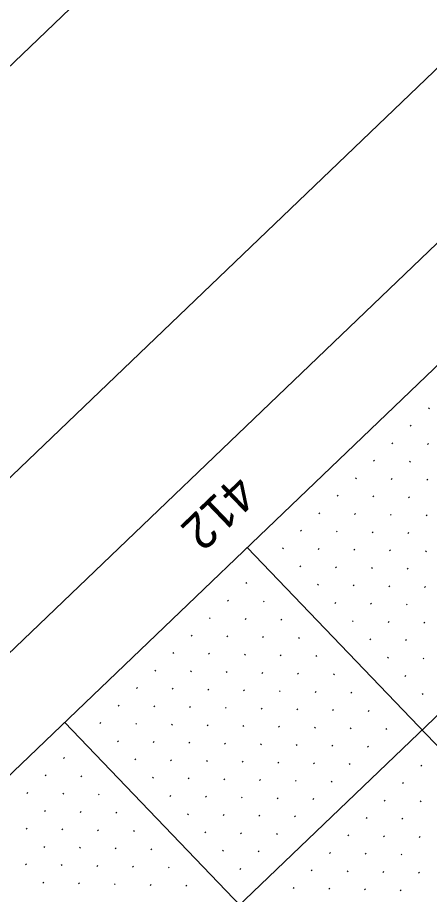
# Model space of a CAD drawing. Extents: x 2148987 to 2151117, y 142806 to 144993.
# Drawn here: x 2149649.5 to 2149731, y 144141.4 to 144315 of the extents above; entities that cross this region are included whole.
import ezdxf

# ---------------------------------------------------------------- set-up
doc = ezdxf.new("R2010")
doc.units = 0
for name, color, linetype in [('BASELINE', 7, 'Continuous'), ('PR_ABUT_PH3', 7, 'Continuous'), ('PR_PIER_PH3', 7, 'Continuous'), ('PR_Road_Concrete', 7, 'Continuous'), ('SHT_Profile_Grid_Minor', 7, 'Continuous'), ('Wall D Bore Txt', 7, 'Continuous')]:
    doc.layers.add(name, color=color, linetype=linetype)

msp = doc.modelspace()

# ---------------------------------------------------------------- linework, layer by layer
at = {"layer": 'BASELINE'}
msp.add_lwpolyline([(2151029.45, 144024.32), (2149802.07, 142848.08), (2149040.98, 143642.27), (2150268.36, 144818.51)], close=True, dxfattribs=at)
at = {"layer": 'PR_ABUT_PH3'}
msp.add_lwpolyline([(2151117.11, 144051.19), (2149817.52, 142805.76), (2148987.24, 143672.15), (2150286.82, 144917.58)], close=True, dxfattribs=at)
at = {"layer": 'PR_PIER_PH3'}
for p, q in [((2150261.97, 144684.26), (2149124.83, 143594.52)), ((2149694.9, 144210.09), (2149989.02, 143903.18)), ((2149658.8, 144175.49), (2149952.92, 143868.59))]:
    msp.add_line(p, q, dxfattribs=at)
at = {"layer": 'PR_Road_Concrete'}
msp.add_line((2150227.37, 144720.36), (2149279.76, 143812.24), dxfattribs=at)
msp.add_lwpolyline([(2150941.76, 143974.91), (2149804.63, 142885.16), (2149078.13, 143643.25), (2150215.26, 144733)], close=True, dxfattribs=at)
at = {"layer": 'SHT_Profile_Grid_Minor'}
for p, q in [((2149730.94, 144237.7), (2149730.76, 144237.52)), ((2149727.33, 144234.24), (2149727.15, 144234.06)), ((2149723.72, 144230.78), (2149723.54, 144230.61)), ((2149730.79, 144230.63), (2149730.61, 144230.45)), ((2149720.11, 144227.32), (2149719.93, 144227.15)), ((2149727.18, 144227.17), (2149727, 144227)), ((2149716.5, 144223.86), (2149716.32, 144223.69)), ((2149723.57, 144223.71), (2149723.39, 144223.54)), ((2149730.64, 144223.56), (2149730.46, 144223.39)), ((2149712.89, 144220.4), (2149712.71, 144220.23)), ((2149719.96, 144220.25), (2149719.78, 144220.08)), ((2149727.03, 144220.1), (2149726.85, 144219.93)), ((2149709.28, 144216.94), (2149709.1, 144216.77)), ((2149716.35, 144216.79), (2149716.17, 144216.62)), ((2149723.42, 144216.64), (2149723.24, 144216.47)), ((2149730.49, 144216.49), (2149730.31, 144216.32)), ((2149705.67, 144213.48), (2149705.49, 144213.31)), ((2149712.74, 144213.33), (2149712.56, 144213.16)), ((2149719.81, 144213.18), (2149719.63, 144213.01)), ((2149726.88, 144213.03), (2149726.7, 144212.86)), ((2149702.06, 144210.02), (2149701.88, 144209.85)), ((2149709.13, 144209.87), (2149708.95, 144209.7)), ((2149716.2, 144209.72), (2149716.02, 144209.55)), ((2149723.27, 144209.57), (2149723.09, 144209.4)), ((2149730.34, 144209.42), (2149730.16, 144209.25)), ((2149705.52, 144206.41), (2149705.34, 144206.24)), ((2149712.59, 144206.26), (2149712.41, 144206.09)), ((2149719.66, 144206.11), (2149719.48, 144205.94)), ((2149726.73, 144205.96), (2149726.55, 144205.79)), ((2149694.84, 144203.1), (2149694.66, 144202.93)), ((2149708.98, 144202.8), (2149708.8, 144202.63)), ((2149716.05, 144202.65), (2149715.87, 144202.48)), ((2149723.12, 144202.5), (2149722.94, 144202.33)), ((2149730.19, 144202.35), (2149730.01, 144202.18)), ((2149691.23, 144199.64), (2149691.05, 144199.47)), ((2149698.3, 144199.49), (2149698.12, 144199.32)), ((2149712.44, 144199.19), (2149712.26, 144199.02)), ((2149719.51, 144199.04), (2149719.33, 144198.87)), ((2149726.58, 144198.89), (2149726.4, 144198.72)), ((2149687.62, 144196.18), (2149687.44, 144196.01)), ((2149694.69, 144196.03), (2149694.51, 144195.86)), ((2149701.76, 144195.88), (2149701.58, 144195.71)), ((2149715.9, 144195.58), (2149715.72, 144195.41)), ((2149722.97, 144195.43), (2149722.79, 144195.26)), ((2149730.04, 144195.28), (2149729.86, 144195.11)), ((2149684.01, 144192.72), (2149683.83, 144192.55)), ((2149691.08, 144192.57), (2149690.9, 144192.4)), ((2149698.15, 144192.42), (2149697.97, 144192.25)), ((2149705.22, 144192.27), (2149705.04, 144192.1)), ((2149719.36, 144191.97), (2149719.18, 144191.8)), ((2149726.43, 144191.82), (2149726.25, 144191.65)), ((2149680.4, 144189.26), (2149680.22, 144189.09)), ((2149687.47, 144189.11), (2149687.29, 144188.94)), ((2149694.54, 144188.96), (2149694.36, 144188.79)), ((2149701.61, 144188.81), (2149701.43, 144188.64)), ((2149708.68, 144188.66), (2149708.5, 144188.49)), ((2149722.82, 144188.36), (2149722.64, 144188.19)), ((2149729.89, 144188.21), (2149729.71, 144188.04)), ((2149676.79, 144185.8), (2149676.61, 144185.63)), ((2149683.86, 144185.65), (2149683.68, 144185.48)), ((2149690.93, 144185.5), (2149690.75, 144185.33)), ((2149698, 144185.35), (2149697.82, 144185.18)), ((2149705.07, 144185.2), (2149704.89, 144185.03)), ((2149712.14, 144185.05), (2149711.96, 144184.88)), ((2149726.28, 144184.75), (2149726.1, 144184.58)), ((2149673.18, 144182.35), (2149673, 144182.17)), ((2149680.25, 144182.19), (2149680.07, 144182.02)), ((2149687.32, 144182.04), (2149687.14, 144181.87)), ((2149694.39, 144181.89), (2149694.21, 144181.72)), ((2149701.46, 144181.74), (2149701.28, 144181.57)), ((2149708.53, 144181.59), (2149708.35, 144181.42)), ((2149715.6, 144181.44), (2149715.42, 144181.27)), ((2149729.74, 144181.14), (2149729.56, 144180.97)), ((2149669.57, 144178.89), (2149669.39, 144178.71)), ((2149676.64, 144178.74), (2149676.46, 144178.56)), ((2149683.71, 144178.58), (2149683.53, 144178.41)), ((2149690.78, 144178.43), (2149690.6, 144178.26)), ((2149697.85, 144178.28), (2149697.67, 144178.11)), ((2149704.92, 144178.13), (2149704.74, 144177.96)), ((2149711.99, 144177.98), (2149711.81, 144177.81)), ((2149719.06, 144177.83), (2149718.88, 144177.66)), ((2149665.96, 144175.43), (2149665.78, 144175.25)), ((2149673.03, 144175.28), (2149672.85, 144175.1)), ((2149680.1, 144175.13), (2149679.92, 144174.95)), ((2149687.17, 144174.97), (2149686.99, 144174.8)), ((2149694.24, 144174.82), (2149694.06, 144174.65)), ((2149701.31, 144174.67), (2149701.13, 144174.5)), ((2149708.38, 144174.52), (2149708.2, 144174.35)), ((2149715.45, 144174.37), (2149715.27, 144174.2)), ((2149722.52, 144174.22), (2149722.34, 144174.05)), ((2149669.42, 144171.82), (2149669.24, 144171.64)), ((2149676.49, 144171.67), (2149676.31, 144171.49)), ((2149683.56, 144171.52), (2149683.38, 144171.34)), ((2149690.63, 144171.36), (2149690.45, 144171.19)), ((2149697.7, 144171.21), (2149697.52, 144171.04)), ((2149704.77, 144171.06), (2149704.59, 144170.89)), ((2149711.84, 144170.91), (2149711.66, 144170.74)), ((2149718.91, 144170.76), (2149718.73, 144170.59)), ((2149658.74, 144168.51), (2149658.56, 144168.33)), ((2149672.88, 144168.21), (2149672.7, 144168.03)), ((2149679.95, 144168.06), (2149679.77, 144167.88)), ((2149687.02, 144167.91), (2149686.84, 144167.73)), ((2149694.09, 144167.75), (2149693.91, 144167.58)), ((2149701.16, 144167.6), (2149700.98, 144167.43)), ((2149708.23, 144167.45), (2149708.05, 144167.28)), ((2149715.3, 144167.3), (2149715.12, 144167.13)), ((2149729.44, 144167), (2149729.26, 144166.83)), ((2149655.13, 144165.05), (2149654.95, 144164.87)), ((2149662.2, 144164.9), (2149662.02, 144164.72)), ((2149676.34, 144164.6), (2149676.16, 144164.42)), ((2149683.41, 144164.45), (2149683.23, 144164.27)), ((2149690.48, 144164.3), (2149690.3, 144164.12)), ((2149697.55, 144164.15), (2149697.37, 144163.97)), ((2149704.62, 144163.99), (2149704.44, 144163.82)), ((2149711.69, 144163.84), (2149711.51, 144163.67)), ((2149725.83, 144163.54), (2149725.65, 144163.37)), ((2149651.52, 144161.59), (2149651.34, 144161.42)), ((2149658.59, 144161.44), (2149658.41, 144161.26)), ((2149665.66, 144161.29), (2149665.48, 144161.11)), ((2149679.8, 144160.99), (2149679.62, 144160.81)), ((2149686.87, 144160.84), (2149686.69, 144160.66)), ((2149693.94, 144160.69), (2149693.76, 144160.51)), ((2149701.01, 144160.54), (2149700.83, 144160.36)), ((2149708.08, 144160.38), (2149707.9, 144160.21)), ((2149722.22, 144160.08), (2149722.04, 144159.91)), ((2149729.29, 144159.93), (2149729.11, 144159.76)), ((2149654.98, 144157.98), (2149654.8, 144157.81)), ((2149662.05, 144157.83), (2149661.87, 144157.65)), ((2149669.12, 144157.68), (2149668.94, 144157.5)), ((2149683.26, 144157.38), (2149683.08, 144157.2)), ((2149690.33, 144157.23), (2149690.15, 144157.05)), ((2149697.4, 144157.08), (2149697.22, 144156.9)), ((2149704.47, 144156.93), (2149704.29, 144156.75)), ((2149718.61, 144156.62), (2149718.43, 144156.45)), ((2149725.68, 144156.47), (2149725.5, 144156.3)), ((2149651.37, 144154.52), (2149651.19, 144154.35)), ((2149658.44, 144154.37), (2149658.26, 144154.2)), ((2149665.51, 144154.22), (2149665.33, 144154.04)), ((2149672.58, 144154.07), (2149672.4, 144153.89)), ((2149686.72, 144153.77), (2149686.54, 144153.59)), ((2149693.79, 144153.62), (2149693.61, 144153.44)), ((2149700.86, 144153.47), (2149700.68, 144153.29)), ((2149715, 144153.16), (2149714.82, 144152.99)), ((2149722.07, 144153.01), (2149721.89, 144152.84)), ((2149729.14, 144152.86), (2149728.96, 144152.69)), ((2149654.83, 144150.91), (2149654.65, 144150.74)), ((2149661.9, 144150.76), (2149661.72, 144150.59)), ((2149668.97, 144150.61), (2149668.79, 144150.43)), ((2149676.04, 144150.46), (2149675.86, 144150.28)), ((2149690.18, 144150.16), (2149690, 144149.98)), ((2149697.25, 144150.01), (2149697.07, 144149.83)), ((2149711.39, 144149.71), (2149711.21, 144149.53)), ((2149718.46, 144149.55), (2149718.28, 144149.38)), ((2149725.53, 144149.4), (2149725.35, 144149.23)), ((2149651.22, 144147.45), (2149651.04, 144147.28)), ((2149658.29, 144147.3), (2149658.11, 144147.13)), ((2149665.36, 144147.15), (2149665.18, 144146.98)), ((2149672.43, 144147), (2149672.25, 144146.82)), ((2149679.5, 144146.85), (2149679.32, 144146.67)), ((2149693.64, 144146.55), (2149693.46, 144146.37)), ((2149707.78, 144146.25), (2149707.6, 144146.07)), ((2149714.85, 144146.1), (2149714.67, 144145.92)), ((2149721.92, 144145.94), (2149721.74, 144145.77)), ((2149728.99, 144145.79), (2149728.81, 144145.62)), ((2149654.68, 144143.84), (2149654.5, 144143.67)), ((2149661.75, 144143.69), (2149661.57, 144143.52)), ((2149668.82, 144143.54), (2149668.64, 144143.37)), ((2149675.89, 144143.39), (2149675.71, 144143.21)), ((2149682.96, 144143.24), (2149682.78, 144143.06)), ((2149704.17, 144142.79), (2149703.99, 144142.61)), ((2149711.24, 144142.64), (2149711.06, 144142.46)), ((2149718.31, 144142.49), (2149718.13, 144142.31)), ((2149725.38, 144142.33), (2149725.2, 144142.16))]:
    msp.add_line(p, q, dxfattribs=at)

# ---------------------------------------------------------------- texts
at = {"layer": 'Wall D Bore Txt'}
msp.add_text('412', height=7, rotation=223.7809, dxfattribs=at).set_placement((2149692.62, 144224.87))

doc.saveas('drawing.dxf')
